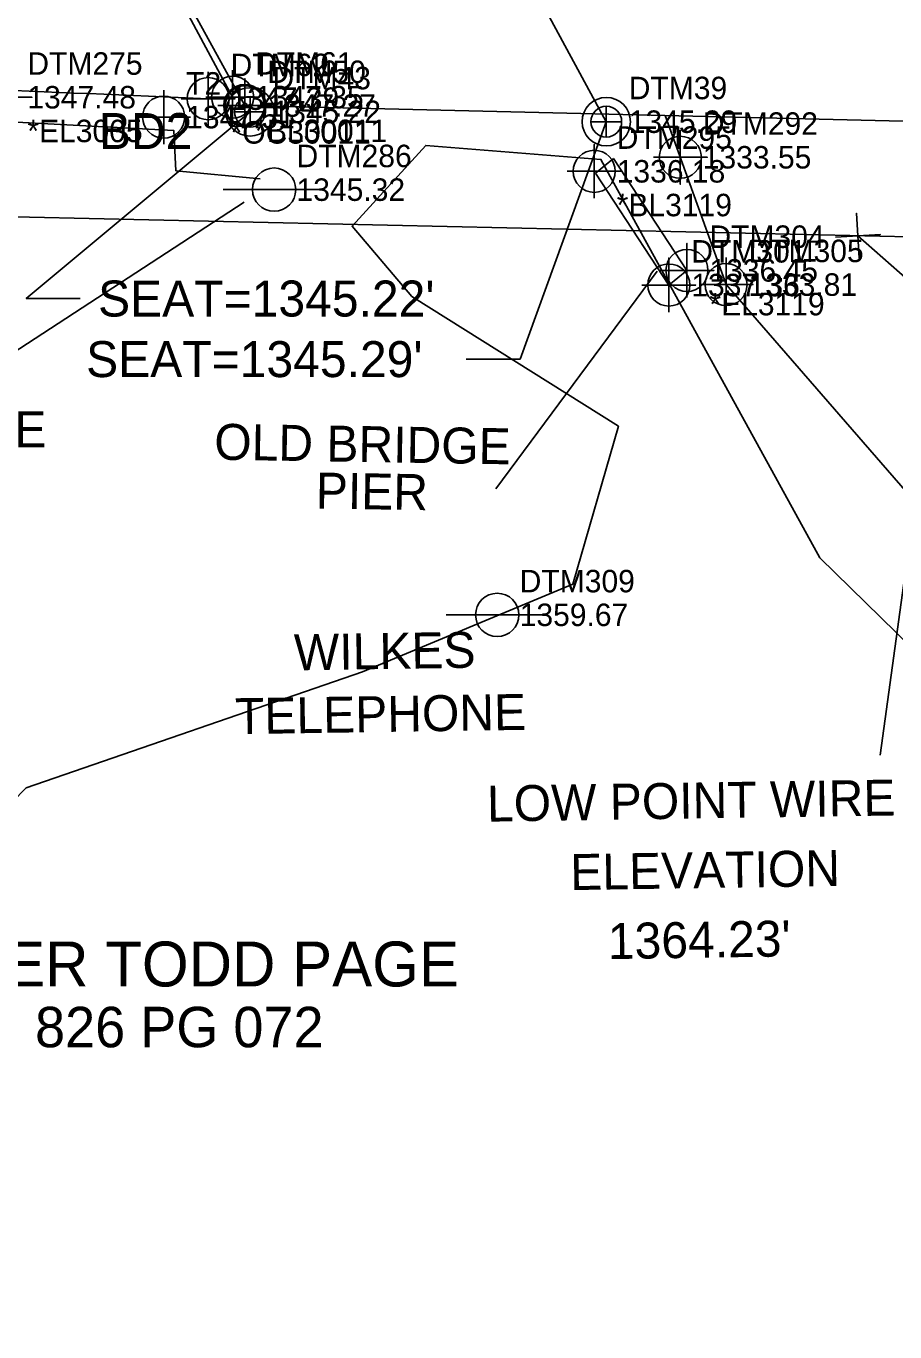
# Model space of a CAD drawing. Extents: x 1303760 to 1305114, y 904598 to 905144.
# Drawn here: x 1304241.8 to 1304338.5, y 904670.7 to 904815.9 of the extents above; entities that cross this region are included whole.
import ezdxf

# ---------------------------------------------------------------- set-up
doc = ezdxf.new("R2010")
doc.units = 0
for name, color, linetype in [('Cogo Default Point CELL', 7, 'Continuous'), ('COGO Default Point Elevation', 7, 'Continuous'), ('COGO Default Point Number', 7, 'Continuous'), ('Exist Hydro Jurisdictional Stream or Body of Water', 7, 'Continuous'), ('Exist Hydro Stream or Body of Water Cogo Elevation', 7, 'Continuous'), ('Exist Hydro Stream or Body of Water Cogo Number', 7, 'Continuous'), ('Exist Hydro Stream or Body of Water Cogo Point CELL', 7, 'Continuous'), ('Exist Other Culture Located Object CELL', 7, 'Continuous'), ('Exist Other Culture Located Object Text', 7, 'Continuous'), ('Exist Property Corner CELL', 7, 'Continuous'), ('Exist Property Deed Book Text', 7, 'Continuous'), ('Exist Property Line', 7, 'Continuous'), ('Exist Property Owner Text', 7, 'Continuous'), ('Exist Right of Way Line', 7, 'Continuous'), ('Exist Roads EOP', 7, 'Continuous'), ('Exist Roads EOP Cogo Comment', 7, 'Continuous'), ('Exist Roads EOP Cogo Elevation', 7, 'Continuous'), ('Exist Roads EOP Cogo Number', 7, 'Continuous'), ('Exist Roads EOP Cogo Point CELL', 7, 'Continuous'), ('Exist Roads Soil Cogo Comment', 7, 'Continuous'), ('Exist Roads Soil Cogo Elevation', 7, 'Continuous'), ('Exist Roads Soil Cogo Number', 7, 'Continuous'), ('Exist Roads Soil Cogo Point CELL', 7, 'Continuous'), ('Exist Structure Major Bridge Seam', 7, 'Continuous'), ('Exist Structure Major Bridge Seat Cogo Point CELL', 7, 'Continuous'), ('Exist Structure Major Bridge Seat Top Elevation', 7, 'Continuous'), ('Exist Structure Major Bridge WW', 7, 'Continuous'), ('Exist Structure Major Bridge WW Cogo Comment', 7, 'Continuous'), ('Exist Structure Major Bridge WW Cogo Elevation', 7, 'Continuous'), ('Exist Structure Major Bridge WW Cogo Number', 7, 'Continuous'), ('Exist Structure Major Bridge WW Cogo Point CELL', 7, 'Continuous'), ('Exist Structure Major Bridge WW Leader', 7, 'Continuous'), ('Exist Structure Major Bridge WW Text', 7, 'Continuous'), ('Exist Structure Major Deck Tunnel Box Culvert', 7, 'Continuous'), ('Exist Structure Major Deck Tunnel Box Culvert Cogo Elevation', 7, 'Continuous'), ('Exist Structure Major Deck Tunnel Box Culvert Cogo Number', 7, 'Continuous'), ('Exist Structure Major Deck Tunnel Box Culvert Cogo Point CELL', 7, 'Continuous'), ('Exist Utilities Other Located Object Leader', 7, 'Continuous'), ('Exist Utilities Other Located Object Text', 7, 'Continuous'), ('Exist Utilities Sanitary Sewer Manhole Cogo Elevation', 7, 'Continuous'), ('Exist Utilities Sanitary Sewer Manhole Cogo Number', 7, 'Continuous'), ('Exist Utilities Telephone Pole CELL', 7, 'Continuous'), ('Exist Utilities Telephone Pole Cogo Elevation', 7, 'Continuous'), ('Exist Utilities Telephone Pole Cogo Number', 7, 'Continuous'), ('Exist Utilities Telephone Pole Leader', 7, 'Continuous'), ('Exist Utilities Telephone Pole Text', 7, 'Continuous'), ('Exist Utilities Telephone UG FO', 7, 'Continuous'), ('Exist Vegetation Woods Line', 7, 'Continuous')]:
    doc.layers.add(name, color=color, linetype=linetype)

# ---------------------------------------------------------------- blocks, each defined once
blk = doc.blocks.new('EXIST OTHER CULTURE LOCATED OBJECT')
at = {"layer": 'Exist Other Culture Located Object CELL'}
for radius in [0.0436, 0.0048]:
    blk.add_circle((0, 0), radius, dxfattribs=at)

msp = doc.modelspace()

# ---------------------------------------------------------------- linework, layer by layer
at = {"layer": 'Cogo Default Point CELL'}
for points in [[(1304257.08, 904808.79), (1304257.08, 904805.79)], [(1304254.08, 904805.79), (1304257.08, 904805.79)], [(1304257.08, 904805.79), (1304260.08, 904805.79)], [(1304257.08, 904805.79), (1304257.08, 904802.79)]]:
    msp.add_lwpolyline(points, dxfattribs=at)
msp.add_circle((1304257.08, 904805.79), 2.34, dxfattribs=at)
at = {"layer": 'Exist Hydro Jurisdictional Stream or Body of Water'}
msp.add_lwpolyline([(1304312.92, 904805.96), (1304319.68, 904787.16), (1304356.37, 904745.03), (1304398.3, 904700.8)], dxfattribs=at)
at = {"layer": 'Exist Hydro Stream or Body of Water Cogo Point CELL'}
for points in [[(1304311.59, 904801.32), (1304317.59, 904801.32), (1304314.59, 904801.32), (1304314.59, 904798.32), (1304314.59, 904804.32)], [(1304316.68, 904787.16), (1304322.68, 904787.16), (1304319.68, 904787.16), (1304319.68, 904784.16), (1304319.68, 904790.16)]]:
    msp.add_lwpolyline(points, dxfattribs=at)
for centre in [(1304314.59, 904801.32), (1304319.68, 904787.16)]:
    msp.add_circle(centre, 2.34, dxfattribs=at)
at = {"layer": 'Exist Property Corner CELL'}
msp.add_line((1304334.36, 904792.6), (1304334.36, 904792.6), dxfattribs=at)
msp.add_lwpolyline([(1304331.87, 904792.45), (1304336.86, 904792.75), (1304334.36, 904792.6), (1304334.21, 904795.09), (1304334.51, 904790.1)], dxfattribs=at)
at = {"layer": 'Exist Property Line'}
msp.add_line((1304334.36, 904792.6), (1304351.87, 904777.06), dxfattribs=at)
at = {"layer": 'Exist Right of Way Line'}
msp.add_line((1304242.14, 904794.67), (1304389.55, 904791.36), dxfattribs=at)
msp.add_arc((1304263.29, 905736.16), 941.73, 256.22599, 268.71327, dxfattribs=at)
at = {"layer": 'Exist Roads EOP'}
msp.add_line((1304264.76, 904808.01), (1304262.03, 904807.84), dxfattribs=at)
msp.add_lwpolyline([(1304252.57, 904830.71), (1304264.76, 904808.01)], dxfattribs=at)
msp.add_spline([(1304262.03, 904807.84), (1304208.94, 904810.39), (1304159.54, 904814.47), (1304108.78, 904821.63), (1304061, 904830.95)], degree=3, dxfattribs=at)
at = {"layer": 'Exist Roads EOP Cogo Point CELL'}
for points in [[(1304262.03, 904810.84), (1304262.03, 904804.84), (1304262.03, 904807.84), (1304265.03, 904807.84), (1304259.03, 904807.84)], [(1304264.76, 904811.01), (1304264.76, 904805.01), (1304264.76, 904808.01), (1304267.76, 904808.01), (1304261.76, 904808.01)]]:
    msp.add_lwpolyline(points, dxfattribs=at)
for centre in [(1304262.03, 904807.84), (1304264.76, 904808.01)]:
    msp.add_circle(centre, 2.34, dxfattribs=at)
at = {"layer": 'Exist Roads Soil Cogo Point CELL'}
msp.add_lwpolyline([(1304239.41, 904805), (1304239.41, 904811), (1304239.41, 904808), (1304242.41, 904808), (1304236.41, 904808)], dxfattribs=at)
at = {"layer": 'Exist Structure Major Bridge Seam'}
msp.add_line((1304292.34, 904831.1), (1304306.35, 904805.28), dxfattribs=at)
at = {"layer": 'Exist Structure Major Bridge Seat Cogo Point CELL'}
for points in [[(1304266.69, 904808.09), (1304266.69, 904804.66), (1304266.69, 904806.37), (1304268.4, 904806.37), (1304264.98, 904806.37)], [(1304306.35, 904806.99), (1304306.35, 904803.57), (1304306.35, 904805.28), (1304308.06, 904805.28), (1304304.63, 904805.28)]]:
    msp.add_lwpolyline(points, dxfattribs=at)
for centre, radius in [((1304266.69, 904806.37), 2.69), ((1304266.69, 904806.37), 1.71), ((1304306.35, 904805.28), 2.69), ((1304306.35, 904805.28), 1.71)]:
    msp.add_circle(centre, radius, dxfattribs=at)
at = {"layer": 'Exist Structure Major Bridge Seat Top Elevation'}
for points in [[(1304266.69, 904806.37), (1304241.78, 904785.61), (1304247.78, 904785.61)], [(1304306.35, 904805.28), (1304296.76, 904778.87), (1304290.76, 904778.87)]]:
    msp.add_lwpolyline(points, dxfattribs=at)
at = {"layer": 'Exist Structure Major Bridge WW'}
for p, q in [((1304305.15, 904799.55), (1304307.17, 904801.18)), ((1304307.17, 904801.18), (1304315.33, 904788.74))]:
    msp.add_line(p, q, dxfattribs=at)
for points in [[(1304305.15, 904799.55), (1304313.31, 904787.11)], [(1304313.31, 904787.11), (1304315.33, 904788.74)]]:
    msp.add_lwpolyline(points, dxfattribs=at)
at = {"layer": 'Exist Structure Major Bridge WW Cogo Point CELL'}
for points in [[(1304302.01, 904799.76), (1304308.01, 904799.76), (1304305.01, 904799.76), (1304305.01, 904802.76), (1304305.01, 904796.76)], [(1304312.33, 904788.74), (1304318.33, 904788.74), (1304315.33, 904788.74), (1304315.33, 904791.74), (1304315.33, 904785.74)], [(1304310.31, 904787.11), (1304316.31, 904787.11), (1304313.31, 904787.11), (1304313.31, 904790.11), (1304313.31, 904784.11)]]:
    msp.add_lwpolyline(points, dxfattribs=at)
for centre in [(1304305.01, 904799.76), (1304315.33, 904788.74), (1304313.31, 904787.11)]:
    msp.add_circle(centre, 2.34, dxfattribs=at)
at = {"layer": 'Exist Structure Major Bridge WW Leader'}
msp.add_line((1304312.01, 904788.66), (1304294.07, 904764.45), dxfattribs=at)
at = {"layer": 'Exist Structure Major Deck Tunnel Box Culvert'}
msp.add_lwpolyline([(1304386.13, 904804.22), (1304266.12, 904807.08), (1304252.84, 904831.27), (1304373.34, 904828.49), (1304386.13, 904804.22)], dxfattribs=at)
at = {"layer": 'Exist Structure Major Deck Tunnel Box Culvert Cogo Point CELL'}
msp.add_lwpolyline([(1304263.12, 904807.08), (1304269.12, 904807.08), (1304266.12, 904807.08), (1304266.12, 904810.08), (1304266.12, 904804.08)], dxfattribs=at)
msp.add_circle((1304266.12, 904807.08), 2.34, dxfattribs=at)
at = {"layer": 'Exist Utilities Other Located Object Leader'}
msp.add_line((1304346.86, 904807.85), (1304336.83, 904734.83), dxfattribs=at)
at = {"layer": 'Exist Utilities Telephone Pole CELL'}
for p, q in [((1304263.7, 904797.72), (1304275.04, 904797.72)), ((1304269.37, 904797.72), (1304269.37, 904797.72)), ((1304288.54, 904750.42), (1304299.88, 904750.42)), ((1304294.21, 904750.42), (1304294.21, 904750.42))]:
    msp.add_line(p, q, dxfattribs=at)
for centre in [(1304269.37, 904797.72), (1304294.21, 904750.42)]:
    msp.add_circle(centre, 2.41, dxfattribs=at)
at = {"layer": 'Exist Utilities Telephone Pole Leader'}
msp.add_line((1304266.04, 904796.34), (1304240.22, 904779.48), dxfattribs=at)
at = {"layer": 'Exist Utilities Telephone UG FO'}
msp.add_lwpolyline([(1304119.72, 904816.65), (1304189.49, 904807.92), (1304258.23, 904804.29), (1304258.45, 904799.82), (1304267.81, 904798.93)], dxfattribs=at)
at = {"layer": 'Exist Vegetation Woods Line'}
msp.add_lwpolyline([(1304214.49, 904670.67), (1304223.46, 904712.45), (1304241.79, 904731.19), (1304279.23, 904744.08), (1304302.63, 904753.84), (1304307.7, 904771.41), (1304284.69, 904785.85), (1304278.06, 904793.66), (1304286.25, 904802.64), (1304305.75, 904801.08), (1304330.13, 904756.77), (1304396.43, 904691.95)], dxfattribs=at)

# ---------------------------------------------------------------- block references
at = {"layer": 'Exist Other Culture Located Object CELL', "xscale": 50, "yscale": 50}
msp.add_blockref('EXIST OTHER CULTURE LOCATED OBJECT', (1304266.12, 904807.08), dxfattribs=at)

# ---------------------------------------------------------------- texts
at = {"layer": 'COGO Default Point Elevation'}
msp.add_text('1347.51', height=2.5, dxfattribs=at).set_placement((1304259.58, 904804.54))
at = {"layer": 'COGO Default Point Number'}
msp.add_text('T2', height=2.5, dxfattribs=at).set_placement((1304259.58, 904808.29))
at = {"layer": 'Exist Hydro Stream or Body of Water Cogo Elevation'}
for s, p in [('1333.55', (1304317.09, 904800.07)), ('1333.81', (1304322.18, 904785.91))]:
    msp.add_text(s, height=2.5, dxfattribs=at).set_placement(p)
at = {"layer": 'Exist Hydro Stream or Body of Water Cogo Number'}
for s, p in [('DTM292', (1304317.09, 904803.82)), ('DTM305', (1304322.18, 904789.66))]:
    msp.add_text(s, height=2.5, dxfattribs=at).set_placement(p)
at = {"layer": 'Exist Other Culture Located Object Text'}
msp.add_text('BD2', height=4, rotation=0.0257, dxfattribs=at).set_placement((1304249.87, 904802.24))
at = {"layer": 'Exist Property Deed Book Text'}
msp.add_text('DB 826 PG 072', height=4.5, dxfattribs=at).set_placement((1304232.73, 904702.33))
at = {"layer": 'Exist Property Owner Text'}
msp.add_text('HUNTER TODD PAGE', height=5, dxfattribs=at).set_placement((1304220.86, 904709.09))
at = {"layer": 'Exist Roads EOP Cogo Comment'}
for s, p in [('*OC30011', (1304264.53, 904802.84)), ('*BL30011', (1304267.26, 904803.01))]:
    msp.add_text(s, height=2.5, dxfattribs=at).set_placement(p)
at = {"layer": 'Exist Roads EOP Cogo Elevation'}
for s, p in [('1347.39', (1304264.53, 904806.59)), ('1347.35', (1304267.26, 904806.76))]:
    msp.add_text(s, height=2.5, dxfattribs=at).set_placement(p)
at = {"layer": 'Exist Roads EOP Cogo Number'}
for s, p in [('DTM61', (1304267.26, 904810.51)), ('DTM62', (1304264.53, 904810.34))]:
    msp.add_text(s, height=2.5, dxfattribs=at).set_placement(p)
at = {"layer": 'Exist Roads Soil Cogo Comment'}
msp.add_text('*EL3005', height=2.5, dxfattribs=at).set_placement((1304241.91, 904803))
at = {"layer": 'Exist Roads Soil Cogo Elevation'}
msp.add_text('1347.48', height=2.5, dxfattribs=at).set_placement((1304241.91, 904806.75))
at = {"layer": 'Exist Roads Soil Cogo Number'}
msp.add_text('DTM275', height=2.5, dxfattribs=at).set_placement((1304241.91, 904810.5))
at = {"layer": 'Exist Structure Major Bridge Seat Top Elevation'}
for s, p in [("SEAT=1345.22'", (1304249.78, 904783.61)), ("SEAT=1345.29'", (1304248.45, 904776.87))]:
    msp.add_text(s, height=4, dxfattribs=at).set_placement(p)
at = {"layer": 'Exist Structure Major Bridge WW Cogo Comment'}
for s, p in [('*BL3119', (1304307.51, 904794.76)), ('*EL3119', (1304317.83, 904783.74))]:
    msp.add_text(s, height=2.5, dxfattribs=at).set_placement(p)
at = {"layer": 'Exist Structure Major Bridge WW Cogo Elevation'}
for s, p in [('1336.18', (1304307.51, 904798.51)), ('1336.45', (1304317.83, 904787.49)), ('1337.36', (1304315.81, 904785.86))]:
    msp.add_text(s, height=2.5, dxfattribs=at).set_placement(p)
at = {"layer": 'Exist Structure Major Bridge WW Cogo Number'}
for s, p in [('DTM295', (1304307.51, 904802.26)), ('DTM304', (1304317.83, 904791.24)), ('DTM301', (1304315.81, 904789.61))]:
    msp.add_text(s, height=2.5, dxfattribs=at).set_placement(p)
at = {"layer": 'Exist Structure Major Bridge WW Text'}
for s, p in [('OLD BRIDGE', (1304262.69, 904767.69)), ('PIER', (1304273.99, 904762.26))]:
    msp.add_text(s, height=4, rotation=359.0896, dxfattribs=at).set_placement(p)
at = {"layer": 'Exist Structure Major Deck Tunnel Box Culvert Cogo Elevation'}
msp.add_text('1347.27', height=2.5, dxfattribs=at).set_placement((1304268.62, 904805.83))
at = {"layer": 'Exist Structure Major Deck Tunnel Box Culvert Cogo Number'}
msp.add_text('DTM50', height=2.5, dxfattribs=at).set_placement((1304268.62, 904809.58))
at = {"layer": 'Exist Utilities Other Located Object Text'}
for s, p in [('LOW POINT WIRE ', (1304293.1, 904727.42)), ('ELEVATION', (1304302.37, 904719.81)), ("1364.23'", (1304306.55, 904712.13))]:
    msp.add_text(s, height=4, rotation=0.8742, dxfattribs=at).set_placement(p)
at = {"layer": 'Exist Utilities Sanitary Sewer Manhole Cogo Elevation'}
for s, p in [('1345.22', (1304269.19, 904805.12)), ('1345.29', (1304308.85, 904804.03))]:
    msp.add_text(s, height=2.5, dxfattribs=at).set_placement(p)
at = {"layer": 'Exist Utilities Sanitary Sewer Manhole Cogo Number'}
for s, p in [('DTM43', (1304269.19, 904808.88)), ('DTM39', (1304308.85, 904807.78))]:
    msp.add_text(s, height=2.5, dxfattribs=at).set_placement(p)
at = {"layer": 'Exist Utilities Telephone Pole Cogo Elevation'}
for s, p in [('1345.32', (1304271.87, 904796.47)), ('1359.67', (1304296.71, 904749.18))]:
    msp.add_text(s, height=2.5, dxfattribs=at).set_placement(p)
at = {"layer": 'Exist Utilities Telephone Pole Cogo Number'}
for s, p in [('DTM286', (1304271.87, 904800.22)), ('DTM309', (1304296.71, 904752.93))]:
    msp.add_text(s, height=2.5, dxfattribs=at).set_placement(p)
at = {"layer": 'Exist Utilities Telephone Pole Text'}
msp.add_text('TELEPHONE', height=4, dxfattribs=at).set_placement((1304211.64, 904769.05))
for s, p in [('WILKES ', (1304271.61, 904744.25)), ('TELEPHONE', (1304265.05, 904737.15))]:
    msp.add_text(s, height=4, rotation=0.8625, dxfattribs=at).set_placement(p)

doc.saveas('drawing.dxf')
